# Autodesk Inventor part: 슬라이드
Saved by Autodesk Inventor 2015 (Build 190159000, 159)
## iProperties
Created: 2025-08
Part Number: 슬라이드
Material: 일반
Document SubType Name: Modeling
Designer: USER
Density: 1 g/cm^3
Appearance: 기본값
Author: USER
Author: jhkim
Creation Date: 2025-08-05
Sending System: Autodesk Inventor 2026
Preprocessor: ST-DEVELOPER v20.1
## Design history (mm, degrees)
node "슬라이드1"
node "솔리드1"
node "기준1"
